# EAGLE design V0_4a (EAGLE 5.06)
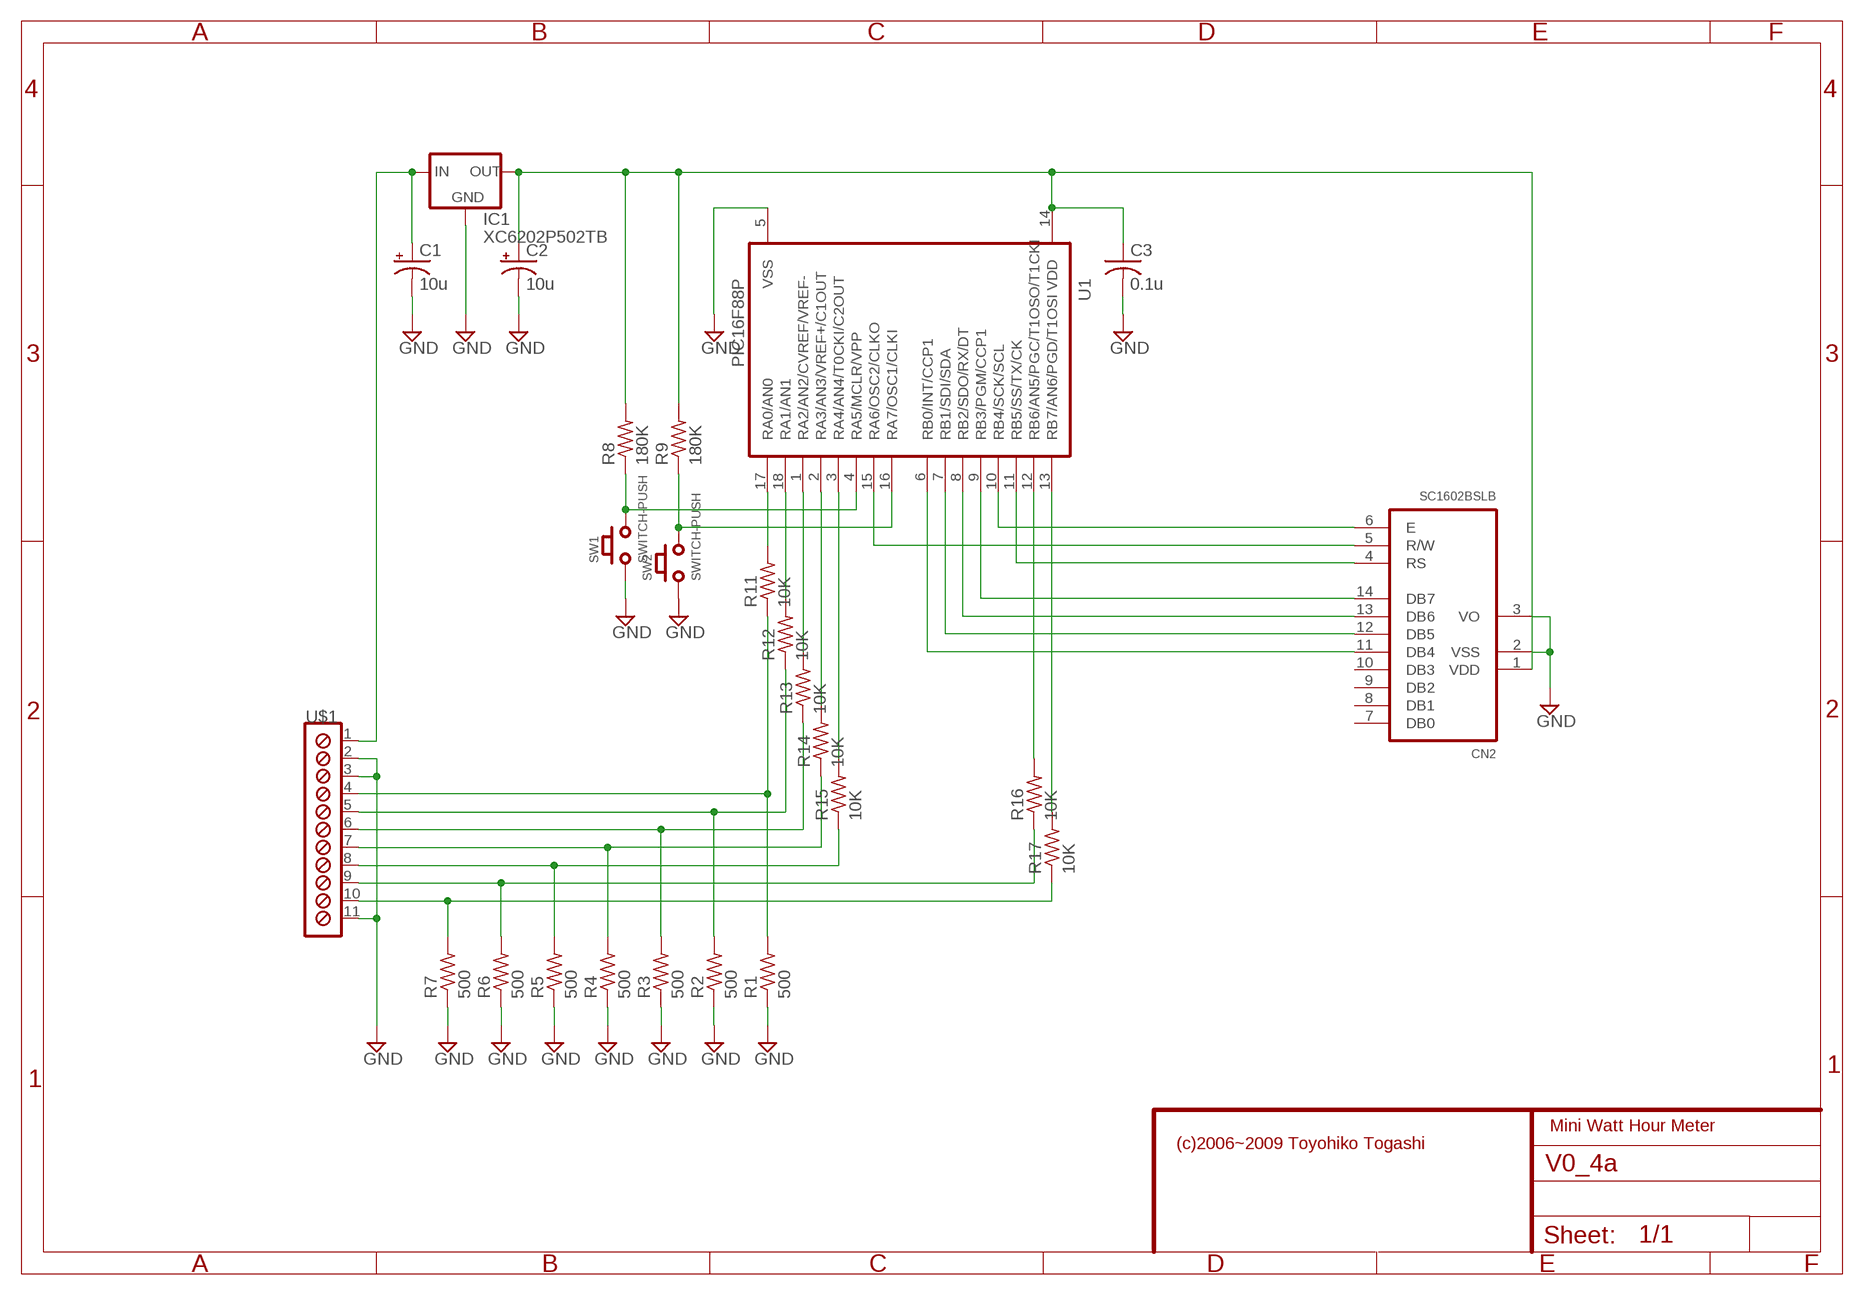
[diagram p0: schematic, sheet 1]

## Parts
C1  10u  CPOL-USE2.5-6  [E2,5-6]
C2  10u  CPOL-USE2.5-6  [E2,5-6]
C3  0.1u  C-US025-024X044  [C025-024X044]
CN2  SC1602BSLB  [MA07-2]
IC1  XC6202P502TB  78LXX  [78LXX]
R1  500  R-US_0204/7  [0204/7]
R2  500  R-US_0204/7  [0204/7]
R3  500  R-US_0204/7  [0204/7]
R4  500  R-US_0204/7  [0204/7]
R5  500  R-US_0204/7  [0204/7]
R6  500  R-US_0204/7  [0204/7]
R7  500  R-US_0204/7  [0204/7]
R8  180K  R-US_0204/7  [0204/7]
R9  180K  R-US_0204/7  [0204/7]
R11  10K  R-US_0204/7  [0204/7]
R12  10K  R-US_0204/7  [0204/7]
R13  10K  R-US_0204/7  [0204/7]
R14  10K  R-US_0204/7  [0204/7]
R15  10K  R-US_0204/7  [0204/7]
R16  10K  R-US_0204/7  [0204/7]
R17  10K  R-US_0204/7  [0204/7]
SW1  SWITCH-PUSH  [SWITCH-PUSH]
SW2  SWITCH-PUSH  [SWITCH-PUSH]
U1  PIC16F88P  [DIL18]
U$1  CONN-SCREW-11P  [CONN-SCREW-11P]

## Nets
CN1: C2.+ C3.1 CN2.1(VDD) IC1.OUT R8.2 R9.2 U1.14(VDD)
N$2: C1.+ IC1.IN U$1.1
N$6: R11.2 U1.17(RA0/AN0)
N$7: R16.2 U1.12(RB6/AN5/PGC/T1OSO/T1CKI)
N$8: R12.2 U1.18(RA1/AN1)
N$10: R6.2 R16.1 U$1.9
N$11: R13.2 U1.1(RA2/AN2/CVREF/VREF-)
N$13: R14.2 U1.2(RA3/AN3/VREF+/C1OUT)
N$14: R17.2 U1.13(RB7/AN6/PGD/T1OSI)
N$15: CN2.11(DB4) U1.6(RB0/INT/CCP1)
N$16: CN2.12(DB5) U1.7(RB1/SDI/SDA)
N$17: CN2.13(DB6) U1.8(RB2/SDO/RX/DT)
N$18: CN2.14(DB7) U1.9(RB3/PGM/CCP1)
N$19: CN2.4(RS) U1.11(RB5/SS/TX/CK)
N$20: CN2.5(R/W) U1.15(RA6/OSC2/CLKO)
N$21: CN2.6(E) U1.10(RB4/SCK/SCL)
N$22: R15.2 U1.3(RA4/AN4/T0CKI/C2OUT)
N$23: R8.1 SW1.P$2(A2) U1.4(RA5/MCLR/VPP)
N$24: R9.1 SW2.P$2(A2) U1.16(RA7/OSC1/CLKI)
N$25: C1.- C2.- C3.2 CN2.2(VSS) CN2.3(VO) IC1.GND R1.1 R2.1 R3.1 R4.1 R5.1 R6.1 R7.1 SW1.P$1(A1) SW2.P$1(A1) U1.5(VSS) U$1.2 U$1.3 U$1.11 ; supply symbol labelled GND
N$26: R1.2 R11.1 U$1.4
N$27: R2.2 R12.1 U$1.5
N$30: R3.2 R13.1 U$1.6
N$31: R4.2 R14.1 U$1.7
N$34: R5.2 R15.1 U$1.8
N$37: R7.2 R17.1 U$1.10
Unconnected: CN2.7(DB0) CN2.8(DB1) CN2.9(DB2) CN2.10(DB3)

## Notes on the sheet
- Mini Watt Hour Meter
- (c)2006~2009 Toyohiko Togashi

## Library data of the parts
C1 C2 = rcl:CPOL-US: POLARIZED CAPACITOR, American symbol
C3 = rcl:C-US: CAPACITOR, American symbol
CN2 = TOG:SC1602BSLB
IC1 = v-reg:78LXX: VOLTAGE REGULATOR
R1-R9 R11-R17 = rcl:R-US_: RESISTOR, American symbol
SW1 SW2 = TOG:SWITCH-PUSH
U1 = microchip:PIC16F88
U$1 = TOG:CONN-SCREW-11P

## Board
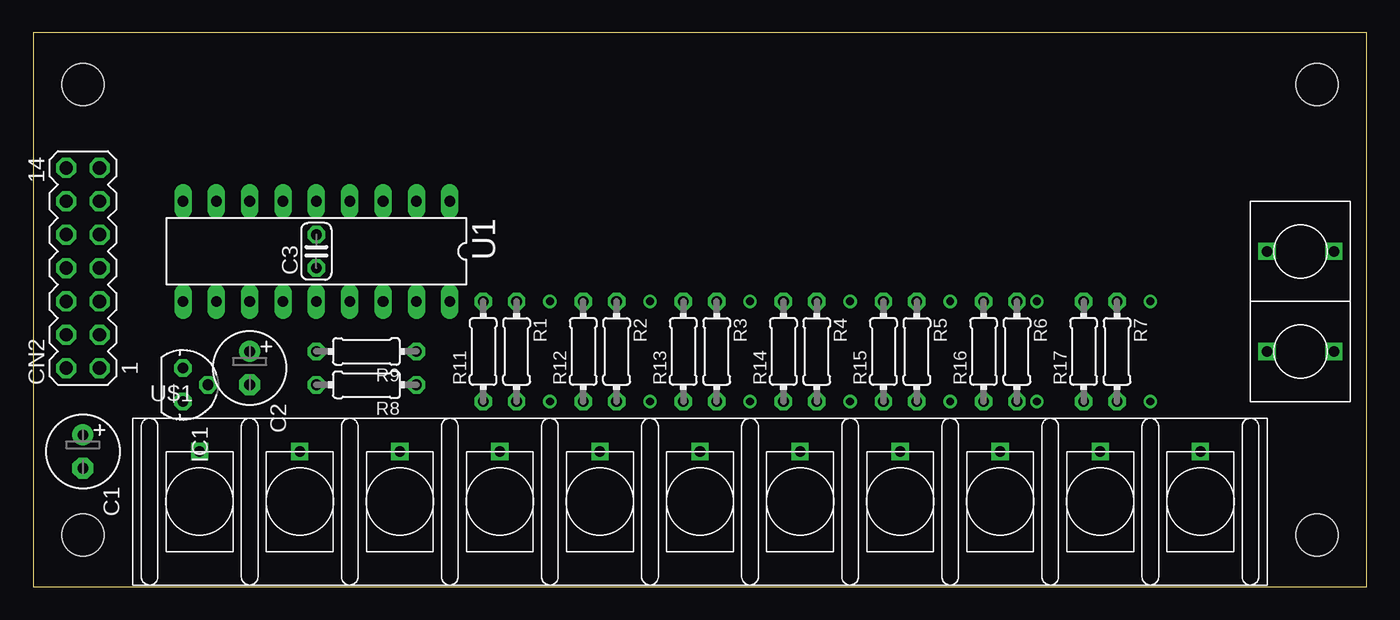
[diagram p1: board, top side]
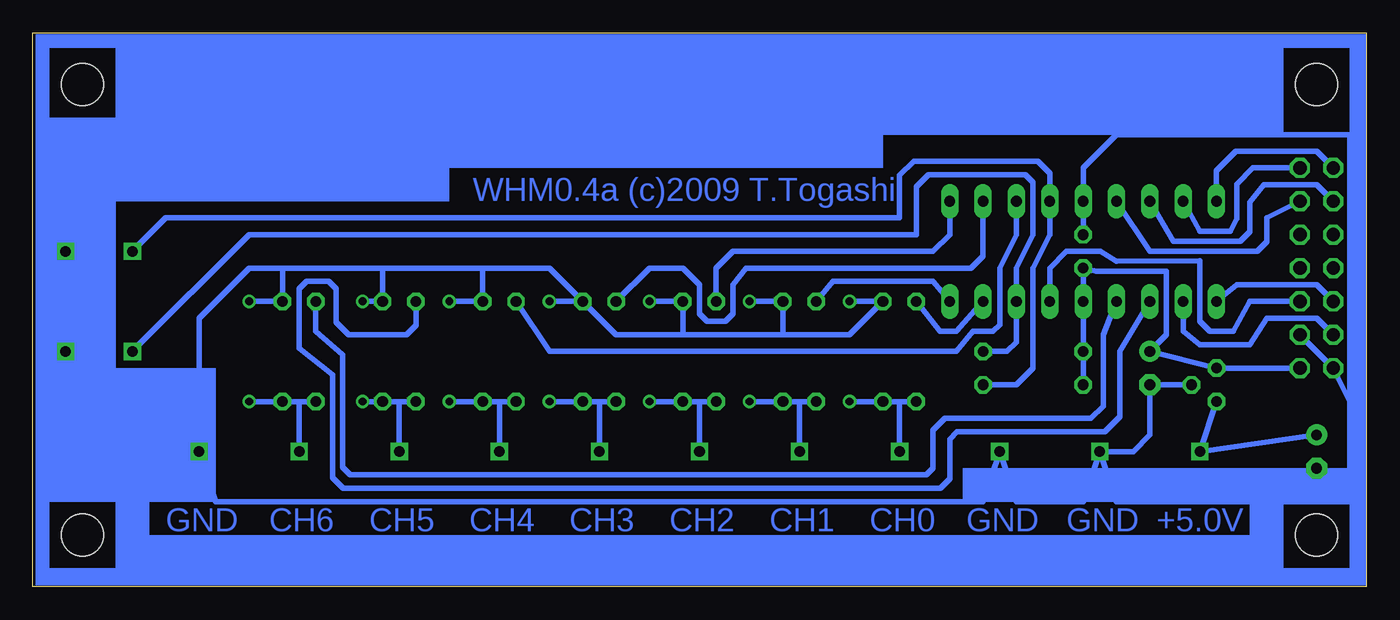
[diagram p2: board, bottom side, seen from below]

Size 101.52 x 42.15 mm. Coordinates in mm from the lower left corner, seen from the top.
Outline: 0,0 101.52,0 101.52,42.15 0,42.15 0,0
Copper layers (1*16): Top 0.035mm / dielectric 1.5mm / Bottom 0.035mm
Design rules "default": minimum track width 10mil, minimum drill 24mil, track to track 8mil, track to pad 8mil, pad to pad 8mil, via to via 8mil, smd to smd 8mil, copper to edge 40mil, drill to drill 8mil, minimum pad ring 10mil, minimum via ring 8mil, stop-mask expansion 4mil, vias tented up to drill 0mil, thermal gap 10mil
Holes 3.2 mm at 3.77,3.93 97.75,3.93 97.75,38.22 3.77,38.22

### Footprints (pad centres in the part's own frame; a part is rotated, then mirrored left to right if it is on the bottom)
E2,5-6 = drill 0.813 pad 1.6 round: + -1.27,0 | drill 0.813 pad 1.6 octagon: - 1.27,0
C025-024X044 = drill 0.813 octagon: 1 -1.27,0; 2 1.27,0
MA07-2 = drill 1.016 octagon: 1 -7.62,-1.27; 2 -7.62,1.27; 3 -5.08,-1.27; 4 -5.08,1.27; 5 -2.54,-1.27; 6 -2.54,1.27; 7 0,-1.27; 8 0,1.27; 9 2.54,-1.27; 10 2.54,1.27; 11 5.08,-1.27; 12 5.08,1.27; 13 7.62,-1.27; 14 7.62,1.27
78LXX = drill 0.813 octagon: GND 0,1.905; IN 1.27,0; OUT -1.27,0
0204/7 = drill 0.813 octagon: 1 -3.81,0; 2 3.81,0
SWITCH-PUSH = drill 0.8 square: P$1 0,2.54; P$2 0,-2.54
DIL18 = drill 0.813 long: 1 -10.16,-3.81; 2 -7.62,-3.81; 3 -5.08,-3.81; 4 -2.54,-3.81; 5 0,-3.81; 6 2.54,-3.81; 7 5.08,-3.81; 8 7.62,-3.81; 9 10.16,-3.81; 10 10.16,3.81; 11 7.62,3.81; 12 5.08,3.81; 13 2.54,3.81; 14 0,3.81; 15 -2.54,3.81; 16 -5.08,3.81; 17 -7.62,3.81; 18 -10.16,3.81
CONN-SCREW-11P = drill 0.8 square: 1 -38.1,3.81; 2 -30.48,3.81; 3 -22.86,3.81; 4 -15.24,3.81; 5 -7.62,3.81; 6 0,3.81; 7 7.62,3.81; 8 15.24,3.81; 9 22.86,3.81; 10 30.48,3.81; 11 38.1,3.81

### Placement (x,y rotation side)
C1  3.77,10.28 270 top
C2  16.47,16.63 270 top
C3  21.55,25.52 90 top
CN2  3.77,24.25 90 top
IC1  11.39,15.36 270 top
R1  36.79,17.9 270 top
R2  44.41,17.9 270 top
R3  52.03,17.9 270 top
R4  59.65,17.9 270 top
R5  67.27,17.9 270 top
R6  74.89,17.9 270 top
R7  82.51,17.9 270 top
R8  25.36,15.36 180 top
R9  25.36,17.9 180 top
R11  34.25,17.9 90 top
R12  41.87,17.9 90 top
R13  49.49,17.9 90 top
R14  57.11,17.9 90 top
R15  64.73,17.9 90 top
R16  72.35,17.9 90 top
R17  79.97,17.9 90 top
SW1  96.48,25.52 270 top
SW2  96.48,17.9 270 top
U1  21.55,25.52 180 top
U$1  50.76,6.47 0 top

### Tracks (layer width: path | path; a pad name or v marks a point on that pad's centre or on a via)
CN1
  Bottom 0.406: CN2.1 IC1.OUT C2.+ 15.2,19.17 15.2,24 20.54,24 C3.1 U1.14 R9.2 R8.2
N$2
  Bottom 0.406: IC1.IN U$1.1 C1.+
N$6
  Bottom 0.406: R11.2 32.47,19.43 31.2,19.43 U1.17
N$7
  Bottom 0.406: R16.2 72.35,19.89 73.07,19.17 77.48,19.17 78.45,20.14 78.45,22.67 79.02,23.24 80.67,23.24 81.24,22.67 81.24,18.16 78.7,16.12 78.7,8.29 77.9,7.49 32.43,7.49 31.71,8.21 31.71,11.24 31.14,11.81 19.89,11.81 18.76,12.94 18.76,17.9 U1.12
N$8
  Bottom 0.406: R12.2 40.6,23.24 32.98,23.24 U1.18
N$10  (via drill 0.6)
  Bottom 0.406: 73.62,14.09 R16.1 | 73.62,14.09 R6.2 v76.42,14.09 | U$1.9 73.62,14.09
N$11
  Bottom 0.406: R13.2 49.49,24.25 48.22,25.52 32.98,25.52 31.71,26.79 U1.1
N$13
  Bottom 0.406: R14.2 54.57,24.25 52.03,24.25 50.76,22.98 50.76,20.76 50.19,20.19 48.79,20.19 48.22,20.76 48.22,22.98 47.21,24.25 30.09,24.25 29.17,25.17 U1.2
N$14
  Bottom 0.406: R17.2 79.97,19.43 77.94,17.65 77.94,9.07 77.37,8.5 33.49,8.5 32.98,9.01 32.98,11.91 32.07,12.82 20.94,12.82 20.03,13.74 20.03,19.17 U1.13
N$15
  Bottom 0.406: CN2.11 7.58,28.06 7.58,26.24 8.3,25.52 16.47,25.52 U1.6
N$16
  Bottom 0.406: CN2.12 3.77,30.6 7.78,30.6 8.85,29.27 8.85,27 9.57,26.28 14.69,26.28 U1.7
N$17
  Bottom 0.406: U1.8 12.66,27.05 10.33,27.05 9.87,28.02 9.87,30.63 8.62,31.9 CN2.13
N$18
  Bottom 0.406: U1.9 11.39,31.66 9.91,33.14 3.77,33.14 CN2.14
N$19
  Bottom 0.406: U1.11 13.93,19.43 12.66,18.41 8.85,18.41 7.58,20.44 3.77,20.44 CN2.4
N$20
  Bottom 0.406: CN2.5 8.85,21.71 10.12,19.43 11.9,19.43 12.66,20.19 12.66,24.8 19.01,24.76 20.24,25.52 22.82,25.52 24.09,24.25 U1.15
N$21
  Bottom 0.406: U1.10 9.87,22.98 3.77,22.98 CN2.6
N$22
  Bottom 0.406: R15.2 62.19,17.9 31.2,17.9 29.93,19.43 28.41,19.43 27.9,19.93 27.9,24.25 26.63,26.79 U1.3
N$23
  Bottom 0.406: SW1.P$2 91.4,28.06 35.52,28.06 35.52,31.3 34.44,32.38 25.01,32.38 24.09,31.46 U1.4 24.09,26.79 25.36,24.25 25.36,16.63 26.63,15.36 R8.1
N$24
  Bottom 0.406: SW2.P$2 85.05,26.79 34.25,26.79 34.25,30.45 33.34,31.36 25.93,31.36 25.36,30.8 25.36,26.79 26.63,24.25 U1.16 26.63,18.62 27.35,17.9 R9.1
N$25  (via drill 0.6)
  Bottom 0.406: U$1.2 21.55,6.47 26.63,6.47 U$1.3 29.17,6.47 87.59,6.47 U$1.11 | U$1.11 97.75,11.55 SW2.P$1 SW1.P$1 | U$1.2 19.01,6.47 3.77,6.47 | U$1.2 17.74,10.28 16.47,11.55 C2.- IC1.GND | CN2.3 CN2.2 1.23,14.09 | 3.77,6.47 1.23,6.47 1.23,14.09 | 3.77,6.47 C1.- | 82.51,24.25 R7.1 v85.05,21.71 | 82.51,24.25 74.89,24.25 | 74.89,24.25 R6.1 v76.42,21.71 | 52.03,19.17 57.11,19.17 R4.1 | 52.03,19.17 44.41,19.17 | 44.41,19.17 39.33,19.17 R1.1 v39.33,21.71 | 44.41,19.17 R2.1 v46.95,21.71 | 52.03,19.17 R3.1 v54.57,21.71 | U1.5 C3.2 21.55,31.87 19.01,34.41 1.23,34.41 1.23,14.09 | 74.89,24.25 67.27,24.25 | 67.27,24.25 62.19,24.25 R4.1 | 67.27,24.25 R5.1 v69.81,21.71 | U$1.11 88.86,20.44 85.05,24.25 82.51,24.25 | v62.19,21.71 R4.1
N$26  (via drill 0.6)
  Bottom 0.406: 35.52,14.09 R11.1 | 35.52,14.09 R1.2 v39.33,14.09 | U$1.4 35.52,14.09
N$27  (via drill 0.6)
  Bottom 0.406: 43.14,14.09 R12.1 | 43.14,14.09 R2.2 v46.95,14.09 | U$1.5 43.14,14.09
N$30  (via drill 0.6)
  Bottom 0.406: 50.76,14.09 R13.1 | 50.76,14.09 R3.2 v54.57,14.09 | U$1.6 50.76,14.09
N$31  (via drill 0.6)
  Bottom 0.406: 58.38,14.09 R14.1 | 58.38,14.09 R4.2 v62.19,14.09 | U$1.7 58.38,14.09
N$34  (via drill 0.6)
  Bottom 0.406: 66,14.09 R15.1 | 66,14.09 R5.2 v69.81,14.09 | U$1.8 66,14.09
N$37  (via drill 0.6)
  Bottom 0.406: 81.24,14.09 R17.1 | 81.24,14.09 R7.2 v85.05,14.09 | U$1.10 81.24,14.09
(copper drawn outside any net)
  shapes: Bottom area x13

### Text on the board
Bottom: WHM0.4a (c)2009 T.Togashi | +5.0V | GND | GND | CH0 | CH1 | CH2 | CH3 | CH4 | CH5 | CH6 | GND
